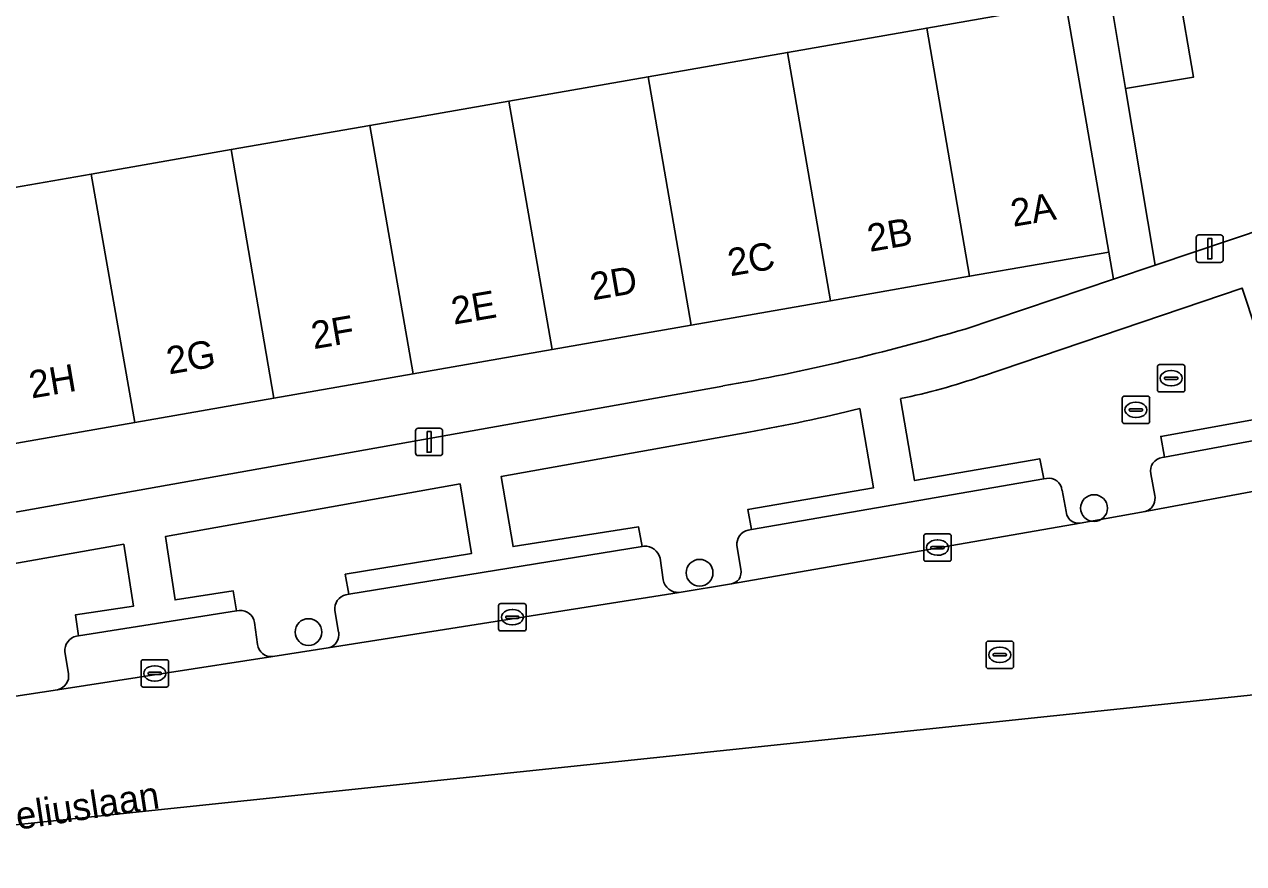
# Model space of a CAD drawing. Extents: x 160157 to 160921, y 381516 to 382045.
# Drawn here: x 160439.93 to 160484.41, y 381516.39 to 381546.99 of the extents above; entities that cross this region are included whole.
import ezdxf

# ---------------------------------------------------------------- set-up
doc = ezdxf.new("R2010")
doc.units = 0
for name, color, linetype in [('IMGEO_Boom', 7, 'Continuous'), ('IMGEO_Erf', 7, 'Continuous'), ('IMGEO_Groenvoorziening', 7, 'Continuous'), ('IMGEO_Kolk', 7, 'Continuous'), ('IMGEO_Lichtmast', 7, 'Continuous'), ('IMGEO_Openbare_ruimte_label', 7, 'Continuous'), ('IMGEO_Pand', 7, 'Continuous'), ('IMGEO_Pand_nummerreeks', 7, 'Continuous'), ('IMGEO_Parkeervlak_open', 7, 'Continuous'), ('IMGEO_Rijbaan_lokaal_gesloten', 7, 'Continuous'), ('IMGEO_Rioolput', 7, 'Continuous'), ('IMGEO_Voetpad_open', 7, 'Continuous')]:
    doc.layers.add(name, color=color, linetype=linetype)

msp = doc.modelspace()

# ---------------------------------------------------------------- linework, layer by layer
at = {"layer": 'IMGEO_Boom'}
for centre in [(160478.955, 381529.354), (160464.563, 381526.996), (160450.295, 381524.834)]:
    msp.add_circle(centre, 0.489, dxfattribs=at)
at = {"layer": 'IMGEO_Erf'}
for points in [[(160476.88, 381554.468), (160476.33, 381557.662), (160475.779, 381560.855), (160478.267, 381561.274), (160478.807, 381558.093), (160479.347, 381554.912), (160478.363, 381554.735), (160479.024, 381551.065), (160481.496, 381551.473), (160482.038, 381548.27), (160482.58, 381545.066), (160480.101, 381544.656), (160481.182, 381538.213), (160501.869, 381545.165)], [(160474.25, 381535.884), (160479.661, 381537.702), (160479.49, 381538.693), (160474.414, 381537.806), (160469.338, 381536.918), (160464.261, 381536.031), (160459.185, 381535.143), (160454.109, 381534.256), (160449.033, 381533.368), (160443.956, 381532.481), (160438.88, 381531.593), (160433.804, 381530.706), (160432.209, 381539.762), (160437.314, 381540.654), (160442.369, 381541.536), (160447.476, 381542.428), (160452.53, 381543.311), (160457.61, 381544.198), (160462.69, 381545.085), (160467.771, 381545.973), (160472.851, 381546.86), (160477.931, 381547.747), (160476.88, 381554.468)], [(160434.753, 381528.34), (160465.414, 381533.807)]]:
    msp.add_lwpolyline(points, dxfattribs=at)
msp.add_arc((160451.739, 381611.815), 79.197, 279.94273, 286.51301, dxfattribs=at)
at = {"layer": 'IMGEO_Groenvoorziening'}
for points in [[(160485.883, 381532.785), (160484.361, 381537.378), (160474.854, 381534.159)], [(160471.895, 381533.345), (160472.407, 381530.356), (160476.976, 381531.157), (160477.119, 381530.423), (160477.218, 381530.44)], [(160470.909, 381530.098), (160470.41, 381532.987)], [(160481.436, 381531.199), (160481.523, 381531.215), (160481.386, 381531.97), (160485.883, 381532.785)], [(160466.355, 381532.125), (160457.326, 381530.511), (160457.757, 381527.949), (160462.335, 381528.674), (160462.466, 381527.952), (160462.534, 381527.964)], [(160481.171, 381529.818), (160481.028, 381530.61)], [(160456.241, 381527.696), (160455.824, 381530.238), (160445.073, 381528.319), (160445.431, 381526.009), (160447.553, 381526.337), (160447.67, 381525.607), (160447.771, 381525.623)], [(160466.341, 381528.553), (160466.452, 381528.572), (160466.322, 381529.303), (160470.909, 381530.098)], [(160477.786, 381530.006), (160477.937, 381529.227)], [(160478.444, 381528.805), (160480.817, 381529.226), (160480.918, 381529.268)], [(160441.794, 381525.46), (160443.915, 381525.784), (160443.558, 381528.038), (160433.809, 381526.312), (160434.562, 381521.724), (160435.377, 381521.853), (160441.143, 381522.733)], [(160466.068, 381527.13), (160465.925, 381527.991)], [(160451.663, 381526.195), (160451.772, 381526.212), (160451.637, 381526.942), (160456.241, 381527.696)], [(160463.122, 381527.525), (160463.236, 381526.742)], [(160463.815, 381526.282), (160465.728, 381526.595)], [(160451.396, 381524.826), (160451.253, 381525.621)], [(160441.828, 381524.688), (160441.906, 381524.701), (160441.794, 381525.46)], [(160448.326, 381525.186), (160448.435, 381524.386)], [(160448.992, 381523.939), (160451.015, 381524.259)], [(160441.537, 381523.318), (160441.404, 381524.112)]]:
    msp.add_lwpolyline(points, dxfattribs=at)
for centre, radius, start, end in [((160466.938, 381557.151), 24.316, 281.7632, 288.9992), ((160455.627, 381592.561), 61.381, 280.06591, 283.93634), ((160481.505, 381530.715), 0.489, 98.1494, 192.4299), ((160477.299, 381529.958), 0.489, 5.651, 99.5833), ((160480.67, 381529.715), 0.511, 298.9878, 11.6074), ((160478.392, 381529.259), 0.456, 184.0233, 251.3488), ((160478.395, 381529.267), 0.465, 251.2844, 276.0352), ((160466.509, 381528.024), 0.584, 146.8865, 183.2102), ((160466.426, 381528.07), 0.49, 100.0318, 146.1909), ((160462.57, 381527.398), 0.567, 12.9135, 93.5966), ((160465.537, 381527.038), 0.539, 329.6496, 9.7961), ((160463.778, 381526.829), 0.548, 189.1485, 273.9191), ((160465.616, 381527.08), 0.497, 283.0255, 320.9101), ((160451.773, 381525.683), 0.523, 102.0895, 186.8351), ((160447.816, 381525.109), 0.516, 8.588, 94.9791), ((160441.953, 381524.152), 0.55, 103.0895, 184.1961), ((160450.919, 381524.735), 0.486, 281.4389, 10.7623), ((160448.939, 381524.444), 0.507, 186.526, 275.979), ((160441.039, 381523.228), 0.506, 281.8859, 10.1932)]:
    msp.add_arc(centre, radius, start, end, dxfattribs=at)
at = {"layer": 'IMGEO_Kolk'}
for p, q in [((160472.744, 381527.489), (160472.744, 381528.341)), ((160472.819, 381528.415), (160473.671, 381528.415)), ((160473.745, 381528.341), (160473.745, 381527.489)), ((160473.003, 381527.909), (160473.003, 381527.921)), ((160473.441, 381527.872), (160473.043, 381527.872)), ((160473.046, 381527.958), (160473.444, 381527.958)), ((160473.232, 381528.195), (160473.257, 381528.195)), ((160473.487, 381527.921), (160473.487, 381527.909)), ((160473.671, 381527.415), (160472.819, 381527.415)), ((160473.255, 381527.635), (160473.23, 381527.635)), ((160457.232, 381524.949), (160457.232, 381525.801)), ((160457.307, 381525.875), (160458.159, 381525.875)), ((160457.72, 381525.655), (160457.745, 381525.655)), ((160458.233, 381525.801), (160458.233, 381524.949)), ((160457.491, 381525.369), (160457.491, 381525.381)), ((160457.929, 381525.332), (160457.531, 381525.332)), ((160457.534, 381525.418), (160457.932, 381525.418)), ((160457.975, 381525.381), (160457.975, 381525.369)), ((160458.159, 381524.875), (160457.307, 381524.875)), ((160457.743, 381525.095), (160457.718, 381525.095)), ((160444.262, 381523.826), (160445.114, 381523.826)), ((160444.187, 381522.9), (160444.187, 381523.752)), ((160444.489, 381523.369), (160444.887, 381523.369)), ((160444.675, 381523.606), (160444.7, 381523.606)), ((160445.188, 381523.752), (160445.188, 381522.9)), ((160444.446, 381523.32), (160444.446, 381523.332)), ((160444.884, 381523.283), (160444.486, 381523.283)), ((160444.698, 381523.046), (160444.673, 381523.046)), ((160444.93, 381523.332), (160444.93, 381523.32)), ((160445.114, 381522.826), (160444.262, 381522.826))]:
    msp.add_line(p, q, dxfattribs=at)
for points in [[(160472.744, 381527.489), (160472.744, 381528.341)], [(160472.819, 381528.415), (160473.671, 381528.415)], [(160473.745, 381528.341), (160473.745, 381527.489)], [(160473.671, 381527.415), (160472.819, 381527.415)], [(160457.232, 381524.949), (160457.232, 381525.801)], [(160457.307, 381525.875), (160458.159, 381525.875)], [(160458.233, 381525.801), (160458.233, 381524.949)], [(160458.159, 381524.875), (160457.307, 381524.875)], [(160444.262, 381523.826), (160445.114, 381523.826)], [(160444.187, 381522.9), (160444.187, 381523.752)], [(160445.188, 381523.752), (160445.188, 381522.9)], [(160445.114, 381522.826), (160444.262, 381522.826)]]:
    msp.add_lwpolyline(points, dxfattribs=at)
for centre, radius, start, end in [((160472.821, 381528.339), 0.0765, 91.552, 178.448), ((160472.821, 381528.339), 0.0765, 91.552, 178.448), ((160473.669, 381528.339), 0.0765, 1.552, 88.448), ((160473.669, 381528.339), 0.0765, 1.552, 88.448), ((160473.043, 381527.918), 0.0403, 85.8775, 175.7526), ((160473.04, 381527.908), 0.0366, 178.938, 274.7102), ((160473.444, 381527.915), 0.043, 264.8664, 352.4533), ((160473.448, 381527.92), 0.0386, 1.7309, 96.639), ((160472.821, 381527.491), 0.0765, 181.552, 268.448), ((160472.821, 381527.491), 0.0765, 181.552, 268.448), ((160473.669, 381527.491), 0.0765, 271.552, 358.448), ((160473.669, 381527.491), 0.0765, 271.552, 358.448), ((160457.309, 381525.799), 0.0765, 91.552, 178.448), ((160457.309, 381525.799), 0.0765, 91.552, 178.448), ((160458.157, 381525.799), 0.0765, 1.552, 88.448), ((160458.157, 381525.799), 0.0765, 1.552, 88.448), ((160457.531, 381525.378), 0.0403, 85.8775, 175.7526), ((160457.528, 381525.368), 0.0366, 178.938, 274.7102), ((160457.932, 381525.375), 0.043, 264.8664, 352.4533), ((160457.936, 381525.38), 0.0386, 1.7309, 96.639), ((160457.309, 381524.951), 0.0765, 181.552, 268.448), ((160457.309, 381524.951), 0.0765, 181.552, 268.448), ((160458.157, 381524.951), 0.0765, 271.552, 358.448), ((160458.157, 381524.951), 0.0765, 271.552, 358.448), ((160444.264, 381523.75), 0.0765, 91.552, 178.448), ((160444.264, 381523.75), 0.0765, 91.552, 178.448), ((160445.112, 381523.75), 0.0765, 1.552, 88.448), ((160445.112, 381523.75), 0.0765, 1.552, 88.448), ((160444.486, 381523.329), 0.0403, 85.8775, 175.7526), ((160444.891, 381523.331), 0.0386, 1.7309, 96.639), ((160444.264, 381522.902), 0.0765, 181.552, 268.448), ((160444.264, 381522.902), 0.0765, 181.552, 268.448), ((160444.483, 381523.319), 0.0366, 178.938, 274.7102), ((160444.887, 381523.326), 0.043, 264.8664, 352.4533), ((160445.112, 381522.902), 0.0765, 271.552, 358.448), ((160445.112, 381522.902), 0.0765, 271.552, 358.448)]:
    msp.add_arc(centre, radius, start, end, dxfattribs=at)
for centre, major_axis, ratio, start_param, end_param in [((160473.231, 381527.915), (-0.387, 0.002), 0.722429, 4.712389, 7.853982), ((160473.256, 381527.915), (-0.39, 0.002), 0.717154, 1.570796, 4.712389), ((160457.719, 381525.375), (-0.387, 0.002), 0.722429, 4.712389, 7.853982), ((160457.744, 381525.375), (-0.39, 0.002), 0.717154, 1.570796, 4.712389), ((160444.674, 381523.326), (-0.387, 0.002), 0.722429, 4.712389, 7.853982), ((160444.699, 381523.326), (-0.39, 0.002), 0.717154, 1.570796, 4.712389)]:
    msp.add_ellipse(centre, major_axis=major_axis, ratio=ratio, start_param=start_param, end_param=end_param, dxfattribs=at)
at = {"layer": 'IMGEO_Lichtmast'}
for p, q in [((160482.681, 381538.416), (160482.681, 381539.216)), ((160482.681, 381539.216), (160482.681, 381538.416)), ((160482.781, 381539.316), (160483.571, 381539.316)), ((160483.571, 381539.316), (160482.781, 381539.316)), ((160483.671, 381539.216), (160483.671, 381538.416)), ((160483.671, 381538.416), (160483.671, 381539.216)), ((160483.571, 381538.316), (160482.781, 381538.316)), ((160482.781, 381538.316), (160483.571, 381538.316)), ((160454.299, 381532.268), (160455.089, 381532.268)), ((160455.089, 381532.268), (160454.299, 381532.268)), ((160454.199, 381531.368), (160454.199, 381532.168)), ((160454.199, 381532.168), (160454.199, 381531.368)), ((160455.189, 381532.168), (160455.189, 381531.368)), ((160455.189, 381531.368), (160455.189, 381532.168)), ((160455.089, 381531.268), (160454.299, 381531.268)), ((160454.299, 381531.268), (160455.089, 381531.268))]:
    msp.add_line(p, q, dxfattribs=at)
for points in [[(160483.101, 381539.191), (160483.251, 381539.191), (160483.251, 381538.441), (160483.101, 381538.441), (160483.101, 381539.191)], [(160454.619, 381532.143), (160454.769, 381532.143), (160454.769, 381531.393), (160454.619, 381531.393), (160454.619, 381532.143)]]:
    msp.add_lwpolyline(points, dxfattribs=at)
for centre, start, end in [((160482.781, 381539.216), 90, 180), ((160482.781, 381539.216), 90, 180), ((160483.571, 381539.216), 0, 90), ((160483.571, 381539.216), 360, 90), ((160482.781, 381538.416), 180, 270), ((160482.781, 381538.416), 180, 270), ((160483.571, 381538.416), 270, 0), ((160483.571, 381538.416), 270, 0), ((160454.299, 381532.168), 90, 180), ((160454.299, 381532.168), 90, 180), ((160455.089, 381532.168), 0, 90), ((160455.089, 381532.168), 360, 90), ((160454.299, 381531.368), 180, 270), ((160454.299, 381531.368), 180, 270), ((160455.089, 381531.368), 270, 0), ((160455.089, 381531.368), 270, 0)]:
    msp.add_arc(centre, 0.1, start, end, dxfattribs=at)
at = {"layer": 'IMGEO_Pand'}
for points in [[(160482.038, 381548.27), (160479.563, 381547.861), (160480.101, 381544.656), (160482.58, 381545.066)], [(160477.931, 381547.747), (160472.851, 381546.86), (160474.414, 381537.806), (160479.49, 381538.693)], [(160472.851, 381546.86), (160467.771, 381545.973), (160469.338, 381536.918), (160474.414, 381537.806)], [(160467.771, 381545.973), (160462.69, 381545.085), (160464.261, 381536.031), (160469.338, 381536.918)], [(160462.69, 381545.085), (160457.61, 381544.198), (160459.185, 381535.143), (160464.261, 381536.031)], [(160457.61, 381544.198), (160452.53, 381543.311), (160454.109, 381534.256), (160459.185, 381535.143)], [(160452.53, 381543.311), (160447.476, 381542.428), (160449.033, 381533.368), (160454.109, 381534.256)], [(160447.476, 381542.428), (160442.369, 381541.536), (160443.956, 381532.481), (160449.033, 381533.368)], [(160442.369, 381541.536), (160437.314, 381540.654), (160438.88, 381531.593), (160443.956, 381532.481)]]:
    msp.add_lwpolyline(points, close=True, dxfattribs=at)
at = {"layer": 'IMGEO_Parkeervlak_open'}
for points in [[(160492.255, 381533.202), (160492.18, 381533.188), (160481.523, 381531.215), (160481.436, 381531.199)], [(160480.918, 381529.268), (160480.817, 381529.226), (160493.5, 381531.587)], [(160481.028, 381530.61), (160481.171, 381529.818)], [(160477.218, 381530.44), (160477.119, 381530.423), (160466.452, 381528.572), (160466.341, 381528.553)], [(160477.937, 381529.227), (160477.786, 381530.006)], [(160465.728, 381526.595), (160478.444, 381528.805)], [(160462.534, 381527.964), (160462.466, 381527.952), (160451.772, 381526.212), (160451.663, 381526.195)], [(160465.925, 381527.991), (160466.068, 381527.13)], [(160463.236, 381526.742), (160463.122, 381527.525)], [(160451.015, 381524.259), (160463.815, 381526.282)], [(160447.67, 381525.607), (160441.906, 381524.701), (160441.828, 381524.688)], [(160447.771, 381525.623), (160447.67, 381525.607)], [(160451.253, 381525.621), (160451.396, 381524.826)], [(160448.435, 381524.386), (160448.326, 381525.186)], [(160441.143, 381522.733), (160448.992, 381523.939)], [(160441.404, 381524.112), (160441.537, 381523.318)]]:
    msp.add_lwpolyline(points, dxfattribs=at)
for centre, radius, start, end in [((160481.505, 381530.715), 0.489, 98.1494, 192.4299), ((160477.299, 381529.958), 0.489, 5.651, 99.5833), ((160480.67, 381529.715), 0.511, 298.9878, 11.6074), ((160478.392, 381529.259), 0.456, 184.0233, 251.3488), ((160478.395, 381529.267), 0.465, 251.2844, 276.0352), ((160466.509, 381528.024), 0.584, 146.8865, 183.2102), ((160466.426, 381528.07), 0.49, 100.0318, 146.1909), ((160462.57, 381527.398), 0.567, 12.9135, 93.5966), ((160465.537, 381527.038), 0.539, 329.6496, 9.7961), ((160463.778, 381526.829), 0.548, 189.1485, 273.9191), ((160465.616, 381527.08), 0.497, 283.0255, 320.9101), ((160451.773, 381525.683), 0.523, 102.0895, 186.8351), ((160447.816, 381525.109), 0.516, 8.588, 94.9791), ((160441.953, 381524.152), 0.55, 103.0895, 184.1961), ((160450.919, 381524.735), 0.486, 281.4389, 10.7623), ((160448.939, 381524.444), 0.507, 186.526, 275.979), ((160441.039, 381523.228), 0.506, 281.8859, 10.1932)]:
    msp.add_arc(centre, radius, start, end, dxfattribs=at)
at = {"layer": 'IMGEO_Rijbaan_lokaal_gesloten'}
for points in [[(160513.931, 381535.305), (160510.743, 381534.735), (160508.639, 381534.334), (160500, 381532.746), (160494.487, 381531.742), (160493.5, 381531.587), (160480.817, 381529.226), (160478.444, 381528.805), (160465.728, 381526.595), (160463.815, 381526.282), (160451.015, 381524.259), (160448.992, 381523.939), (160441.143, 381522.733), (160435.377, 381521.853), (160434.562, 381521.724), (160434.428, 381521.703), (160434.207, 381521.662), (160425.691, 381520.323)], [(160425.691, 381520.323), (160426.156, 381516.392), (160519.058, 381526.148), (160520.971, 381526.488), (160519.788, 381529.587), (160502.108, 381528.076)]]:
    msp.add_lwpolyline(points, dxfattribs=at)
at = {"layer": 'IMGEO_Rioolput'}
for p, q in [((160481.268, 381533.664), (160481.268, 381534.516)), ((160481.343, 381534.59), (160482.195, 381534.59)), ((160482.269, 381534.516), (160482.269, 381533.664)), ((160481.527, 381534.084), (160481.527, 381534.096)), ((160481.965, 381534.047), (160481.567, 381534.047)), ((160481.57, 381534.133), (160481.968, 381534.133)), ((160481.756, 381534.37), (160481.781, 381534.37)), ((160482.011, 381534.096), (160482.011, 381534.084)), ((160482.195, 381533.59), (160481.343, 381533.59)), ((160481.779, 381533.81), (160481.754, 381533.81)), ((160479.983, 381532.511), (160479.983, 381533.363)), ((160480.058, 381533.437), (160480.91, 381533.437)), ((160480.471, 381533.217), (160480.496, 381533.217)), ((160480.984, 381533.363), (160480.984, 381532.511)), ((160480.242, 381532.931), (160480.242, 381532.943)), ((160480.68, 381532.894), (160480.282, 381532.894)), ((160480.285, 381532.98), (160480.683, 381532.98)), ((160480.726, 381532.943), (160480.726, 381532.931)), ((160480.91, 381532.437), (160480.058, 381532.437)), ((160480.494, 381532.657), (160480.469, 381532.657)), ((160475.016, 381523.579), (160475.016, 381524.431)), ((160475.091, 381524.505), (160475.943, 381524.505)), ((160475.504, 381524.285), (160475.529, 381524.285)), ((160476.017, 381524.431), (160476.017, 381523.579)), ((160475.275, 381523.999), (160475.275, 381524.011)), ((160475.713, 381523.962), (160475.315, 381523.962)), ((160475.318, 381524.048), (160475.716, 381524.048)), ((160475.759, 381524.011), (160475.759, 381523.999)), ((160475.943, 381523.505), (160475.091, 381523.505)), ((160475.527, 381523.725), (160475.502, 381523.725))]:
    msp.add_line(p, q, dxfattribs=at)
for points in [[(160481.268, 381533.664), (160481.268, 381534.516)], [(160481.343, 381534.59), (160482.195, 381534.59)], [(160482.269, 381534.516), (160482.269, 381533.664)], [(160482.195, 381533.59), (160481.343, 381533.59)], [(160479.983, 381532.511), (160479.983, 381533.363)], [(160480.058, 381533.437), (160480.91, 381533.437)], [(160480.984, 381533.363), (160480.984, 381532.511)], [(160480.91, 381532.437), (160480.058, 381532.437)], [(160475.016, 381523.579), (160475.016, 381524.431)], [(160475.091, 381524.505), (160475.943, 381524.505)], [(160476.017, 381524.431), (160476.017, 381523.579)], [(160475.943, 381523.505), (160475.091, 381523.505)]]:
    msp.add_lwpolyline(points, dxfattribs=at)
for centre, radius, start, end in [((160481.345, 381534.514), 0.0765, 91.552, 178.448), ((160481.345, 381534.514), 0.0765, 91.552, 178.448), ((160482.193, 381534.514), 0.0765, 1.552, 88.448), ((160482.193, 381534.514), 0.0765, 1.552, 88.448), ((160481.567, 381534.093), 0.0403, 85.8775, 175.7526), ((160481.564, 381534.083), 0.0366, 178.938, 274.7102), ((160481.968, 381534.09), 0.043, 264.8664, 352.4533), ((160481.972, 381534.095), 0.0386, 1.7309, 96.639), ((160481.345, 381533.666), 0.0765, 181.552, 268.448), ((160481.345, 381533.666), 0.0765, 181.552, 268.448), ((160482.193, 381533.666), 0.0765, 271.552, 358.448), ((160482.193, 381533.666), 0.0765, 271.552, 358.448), ((160480.06, 381533.361), 0.0765, 91.552, 178.448), ((160480.06, 381533.361), 0.0765, 91.552, 178.448), ((160480.908, 381533.361), 0.0765, 1.552, 88.448), ((160480.908, 381533.361), 0.0765, 1.552, 88.448), ((160480.282, 381532.94), 0.0403, 85.8775, 175.7526), ((160480.279, 381532.93), 0.0366, 178.938, 274.7102), ((160480.683, 381532.937), 0.043, 264.8664, 352.4533), ((160480.687, 381532.942), 0.0386, 1.7309, 96.639), ((160480.06, 381532.513), 0.0765, 181.552, 268.448), ((160480.06, 381532.513), 0.0765, 181.552, 268.448), ((160480.908, 381532.513), 0.0765, 271.552, 358.448), ((160480.908, 381532.513), 0.0765, 271.552, 358.448), ((160475.093, 381524.429), 0.0765, 91.552, 178.448), ((160475.093, 381524.429), 0.0765, 91.552, 178.448), ((160475.941, 381524.429), 0.0765, 1.552, 88.448), ((160475.941, 381524.429), 0.0765, 1.552, 88.448), ((160475.315, 381524.008), 0.0403, 85.8775, 175.7526), ((160475.312, 381523.998), 0.0366, 178.938, 274.7102), ((160475.716, 381524.005), 0.043, 264.8664, 352.4533), ((160475.72, 381524.01), 0.0386, 1.7309, 96.639), ((160475.093, 381523.581), 0.0765, 181.552, 268.448), ((160475.093, 381523.581), 0.0765, 181.552, 268.448), ((160475.941, 381523.581), 0.0765, 271.552, 358.448), ((160475.941, 381523.581), 0.0765, 271.552, 358.448)]:
    msp.add_arc(centre, radius, start, end, dxfattribs=at)
for centre, major_axis, ratio, start_param, end_param in [((160481.755, 381534.09), (-0.387, 0.002), 0.722429, 4.712389, 7.853982), ((160481.78, 381534.09), (-0.39, 0.002), 0.717154, 1.570796, 4.712389), ((160480.47, 381532.937), (-0.387, 0.002), 0.722429, 4.712389, 7.853982), ((160480.495, 381532.937), (-0.39, 0.002), 0.717154, 1.570796, 4.712389), ((160475.503, 381524.005), (-0.387, 0.002), 0.722429, 4.712389, 7.853982), ((160475.528, 381524.005), (-0.39, 0.002), 0.717154, 1.570796, 4.712389)]:
    msp.add_ellipse(centre, major_axis=major_axis, ratio=ratio, start_param=start_param, end_param=end_param, dxfattribs=at)
at = {"layer": 'IMGEO_Voetpad_open'}
msp.add_lwpolyline([(160480.101, 381544.656), (160479.563, 381547.861), (160479.024, 381551.065), (160478.363, 381554.735), (160476.88, 381554.468), (160477.931, 381547.747), (160479.49, 381538.693), (160479.661, 381537.702), (160481.182, 381538.213)], close=True, dxfattribs=at)
for points in [[(160505.721, 381544.532), (160505.451, 381546.503), (160503.713, 381545.771), (160501.869, 381545.165), (160481.182, 381538.213), (160479.661, 381537.702), (160474.25, 381535.884)], [(160474.854, 381534.159), (160484.361, 381537.378), (160485.883, 381532.785), (160481.386, 381531.97), (160481.523, 381531.215), (160492.18, 381533.188), (160492.04, 381533.938), (160487.403, 381533.066), (160485.804, 381537.855), (160505.721, 381544.532)], [(160465.414, 381533.807), (160434.753, 381528.34), (160429.777, 381527.238), (160429.629, 381527.737)], [(160470.41, 381532.987), (160470.909, 381530.098), (160466.322, 381529.303), (160466.452, 381528.572), (160477.119, 381530.423), (160476.976, 381531.157), (160472.407, 381530.356), (160471.895, 381533.345)], [(160434.207, 381521.662), (160434.428, 381521.703), (160434.562, 381521.724), (160433.809, 381526.312), (160443.558, 381528.038), (160443.915, 381525.784), (160441.794, 381525.46), (160441.906, 381524.701), (160447.67, 381525.607), (160447.553, 381526.337), (160445.431, 381526.009), (160445.073, 381528.319), (160455.824, 381530.238), (160456.241, 381527.696), (160451.637, 381526.942), (160451.772, 381526.212), (160462.466, 381527.952), (160462.335, 381528.674), (160457.757, 381527.949), (160457.326, 381530.511), (160466.355, 381532.125)]]:
    msp.add_lwpolyline(points, dxfattribs=at)
for centre, radius, start, end in [((160451.739, 381611.815), 79.197, 279.94273, 286.51301), ((160466.938, 381557.151), 24.316, 281.7632, 288.9992), ((160455.627, 381592.561), 61.381, 280.06591, 283.93634)]:
    msp.add_arc(centre, radius, start, end, dxfattribs=at)

# ---------------------------------------------------------------- texts
at = {"layer": 'IMGEO_Openbare_ruimte_label'}
msp.add_text('Sibeliuslaan', height=1, rotation=8.6242, dxfattribs=at).set_placement((160437.78, 381517.332))
at = {"layer": 'IMGEO_Pand_nummerreeks'}
for s, p in [('2A', (160476.006, 381539.61)), ('2B', (160470.773, 381538.695)), ('2C', (160465.684, 381537.805)), ('2D', (160460.663, 381536.928)), ('2E', (160455.595, 381536.042)), ('2F', (160450.485, 381535.148)), ('2G', (160445.206, 381534.226)), ('2H', (160440.193, 381533.349))]:
    msp.add_text(s, height=1, rotation=9.7174, dxfattribs=at).set_placement(p)

doc.saveas('drawing.dxf')
